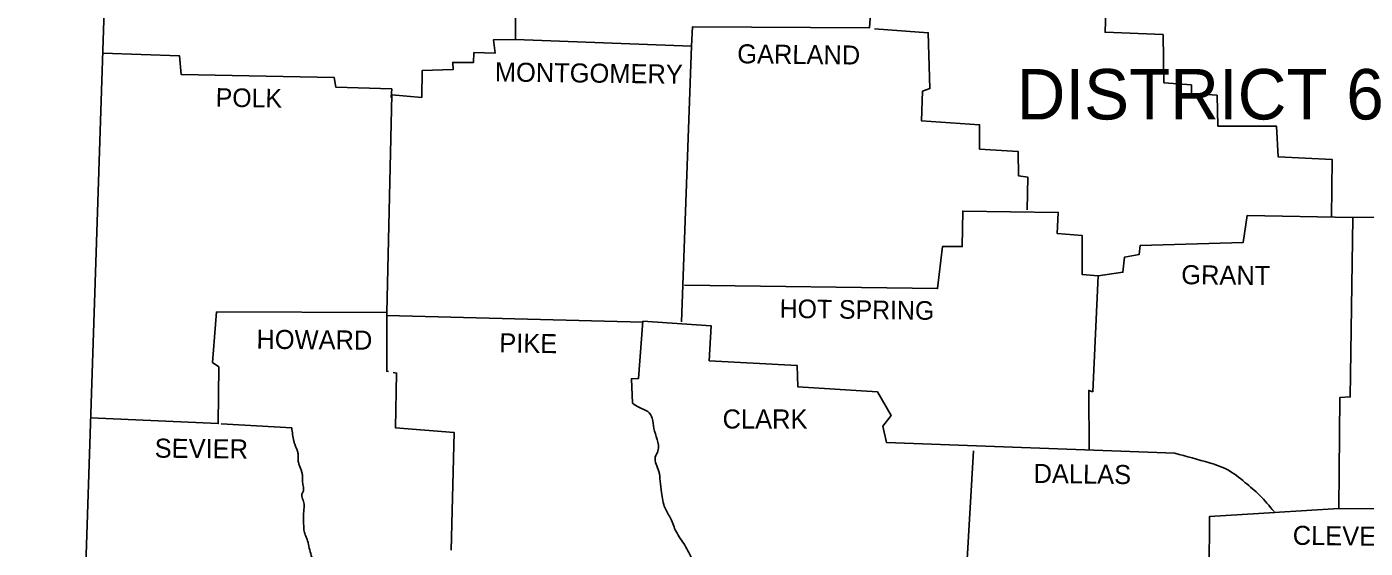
# Model space of a CAD drawing. Extents: x -17742 to 32032, y -17264 to 5867.
# Drawn here: x 1448 to 3114, y 3730 to 4379 of the extents above; entities that cross this region are included whole.
import ezdxf

# ---------------------------------------------------------------- set-up
doc = ezdxf.new("R2010")
doc.units = 0
for name, color, linetype in [('1', 7, 'Continuous'), ('2', 7, 'Continuous'), ('3', 7, 'Continuous')]:
    doc.layers.add(name, color=color, linetype=linetype)

msp = doc.modelspace()

# ---------------------------------------------------------------- linework, layer by layer
at = {"layer": '1'}
for points in [[(1448.3, 5841.4), (1562.2, 4926.7), (1512.7, 3433.6)], [(2057.6, 4685.1), (2056.5, 4363.2), (2028.9, 4362.6), (2031.1, 4346.1), (2004.7, 4346.7), (2004.2, 4334.6), (1978.3, 4334.6), (1978.9, 4325.8), (1940.3, 4324.7), (1939.8, 4291.1), (1902.4, 4294.4), (1896.3, 4023.6), (1684.4, 4024.2), (1679.5, 3961.4), (1687.2, 3955.9), (1686.6, 3885.5), (1527.9, 3892.4)], [(2681.7, 4443), (2501.7, 4448.5), (2496.7, 4377.5), (2276.6, 4378.6), (2275.5, 4354.9)], [(2730.6, 4444.6), (2792.3, 4440.8), (2790.1, 4372), (2862.2, 4369.2), (2863.3, 4309.2), (2897.4, 4306.5), (2897.4, 4296), (2929.3, 4293.8), (2930.4, 4255.3), (3003.1, 4255.3), (3005.3, 4217.3), (3072.4, 4214), (3071.9, 4142.5)], [(2503.3, 4376.4), (2569.9, 4371.4), (2572.1, 4302.1), (2562.8, 4298.8), (2561.7, 4261.9), (2633.8, 4257), (2633.8, 4226.7), (2681.7, 4223.9), (2682.2, 4193.7), (2693.8, 4192), (2693.2, 4151.3)], [(2275.5, 4354.9), (2056.5, 4363.2)], [(2275.5, 4354.9), (2262.8, 4012.1)], [(1543, 4346.1), (1638.2, 4342.8), (1640.4, 4319.7), (1830.8, 4315.8), (1833, 4303.7), (1902.4, 4301.5), (1901.8, 4291.1)], [(3728.4, 4205.8), (3520.4, 4211.3), (3519.3, 4143.6), (3098.3, 4141.9)], [(2266.7, 4057.7), (2581.5, 4053.3), (2587.6, 4105.6), (2612.3, 4105.6), (2612.9, 4149.6), (2731.7, 4148), (2730.6, 4121.6), (2761.5, 4119.4), (2761.5, 4070.9), (2781.3, 4069.3)], [(2781.3, 4069.3), (2812.1, 4073.7), (2814.3, 4092.4), (2832.5, 4095.7), (2833.6, 4106.7), (2961.8, 4110.6), (2966.7, 4144.1), (3098.3, 4141.9)], [(3098.3, 4140.8), (3095, 3918.5), (3082.3, 3917.9), (3080.7, 3779.8)], [(2781.3, 4069.3), (2774.7, 3925.1), (2769.7, 3926.7), (2770.3, 3851.9)], [(1896.3, 4023.6), (1896.3, 3950.4), (1898.6, 3950)], [(1896.3, 4019.8), (2214.9, 4011.4)], [(2201.8, 3910.8), (2200.7, 3941.1), (2209.5, 3941.6), (2215, 4012.6), (2299.7, 4007.1), (2297.5, 3963.6), (2407, 3957.6), (2407.6, 3931.2), (2506.7, 3925.1), (2523.7, 3895.4), (2513.3, 3882.2), (2518.2, 3861.8), (2877, 3848.6)], [(1904.1, 3949), (1908.4, 3948.2), (1907.3, 3880), (1980, 3874.5), (1976.4, 3728.1)], [(1690.4, 3885.2), (1778, 3880)], [(2626.1, 3851.4), (2617.8, 3709.9), (2579.8, 3705.5)], [(3001.4, 3774.9), (2920, 3769.9), (2919.4, 3701.1)], [(3080.7, 3779.8), (3000.3, 3774.9)], [(3080.7, 3779.8), (3275.5, 3778.7)]]:
    msp.add_lwpolyline(points, dxfattribs=at)
for points in [[(2201.8, 3910.8), (2210.6, 3905.3), (2221, 3900.3), (2226.5, 3892.1), (2228.7, 3879.4), (2232.6, 3865.7), (2233.7, 3851.4), (2230.4, 3843.6), (2234.8, 3826), (2236.4, 3813.9), (2238.1, 3799.6), (2242.5, 3780.4), (2249.6, 3767.1), (2256.2, 3751.2), (2267.2, 3734.1), (2276.6, 3715.4), (2281, 3705.5), (2289.3, 3685.1), (2299.7, 3671.4), (2316.2, 3650.5), (2331.1, 3629), (2339.3, 3613), (2352, 3595.4), (2366.3, 3586.6), (2384.5, 3577.3), (2396, 3571.8), (2409.2, 3562.4), (2426.3, 3561.3), (2439, 3561.3), (2450.5, 3556.4), (2456, 3546.5), (2465.9, 3539.9), (2473.6, 3537.6)], [(1778, 3880), (1780.7, 3863.5), (1781.8, 3859.8), (1783.2, 3856.3), (1784.6, 3852.8), (1785.7, 3849.1), (1786, 3846.4), (1786, 3843.7), (1786, 3840.9), (1786.2, 3838.1), (1787.3, 3834), (1788.8, 3829.9), (1790.3, 3825.8), (1791.2, 3821.6), (1791.2, 3815.6), (1791.5, 3812.5), (1792, 3809.5), (1792.5, 3806.5), (1792.8, 3803.5), (1792.5, 3801.8), (1791.8, 3800.2), (1791, 3798.5), (1790.6, 3796.9), (1791.1, 3793.6), (1792.1, 3790.3), (1793, 3787), (1793.4, 3783.7), (1792.8, 3773.8), (1792.8, 3765.5), (1792.9, 3758.6), (1793.1, 3755.2), (1793.4, 3751.7), (1794.2, 3748.6), (1795.4, 3745.6), (1796.7, 3742.7), (1797.8, 3739.6), (1799.9, 3730.5), (1802.2, 3721.5), (1804.9, 3712.1), (1809.4, 3697.8), (1812.1, 3680.2), (1812.7, 3667), (1812.5, 3664), (1812, 3660.9), (1811.6, 3657.9), (1811.6, 3654.9), (1814.9, 3641.1), (1820.9, 3627.4), (1828.6, 3614.1), (1838, 3599.3), (1844.6, 3587.7), (1852.8, 3575.1), (1859.4, 3564.6), (1861.8, 3561.3), (1864.3, 3558), (1866.9, 3554.8), (1869.3, 3551.4), (1873.7, 3540.4), (1874, 3536.6), (1873.8, 3532.7), (1873.6, 3528.8), (1873.7, 3525), (1874.2, 3522), (1874.8, 3519), (1875.8, 3513)], [(2877, 3848.6), (2920, 3836.5), (2942, 3828.2), (2964, 3812.3), (2982.2, 3796.3), (3000.3, 3776)]]:
    msp.add_spline(points, degree=3, dxfattribs=at)

# ---------------------------------------------------------------- texts
at = {"layer": '2'}
for s, height, rotation, p in [('GARLAND', 23.67, 359.3658, (2332.2, 4333.5)), ('MONTGOMERY', 23.67, 359.2944, (2030.6, 4310.9)), ('POLK', 23.11, 359.2152, (1683.3, 4279.5)), ('GRANT', 23.67, 359.4032, (2884.7, 4058.8)), ('HOT SPRING', 23.11, 359.2216, (2385, 4017)), ('HOWARD', 23.67, 359.5145, (1734, 3978.5)), ('PIKE', 23.66, 359.0452, (2036.1, 3974.1)), ('SEVIER', 23.67, 359.4271, (1607.4, 3843.1)), ('DALLAS', 23.66, 359.2462, (2700.9, 3811.7)), ('CLEVELAND', 23.67, 359.3377, (3023.4, 3734.7))]:
    msp.add_text(s, height=height, rotation=rotation, dxfattribs=at).set_placement(p)
msp.add_text('CLARK', height=23.67, dxfattribs=at).set_placement((2314.1, 3879.3))
at = {"layer": '3'}
msp.add_text('DISTRICT 6', height=62.74, dxfattribs=at).set_placement((2680, 4263.6))

doc.saveas('drawing.dxf')
